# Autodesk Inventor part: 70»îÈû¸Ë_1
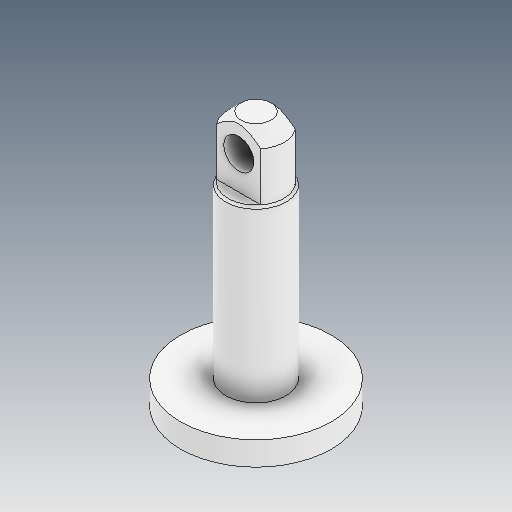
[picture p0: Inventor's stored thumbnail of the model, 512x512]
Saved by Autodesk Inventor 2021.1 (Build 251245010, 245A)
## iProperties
Created: 2021-05
Part Number: 70»îÈû¸Ë_1
Material: Ogólny
Document SubType Name: Modeling
Designer: user
Density: 1 g/cm^3
Appearance: Domyślna
Author: user
Revision Number: ÈÎºÎ
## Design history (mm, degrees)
feature "ÊäÈë1"
node "Bryła1"
